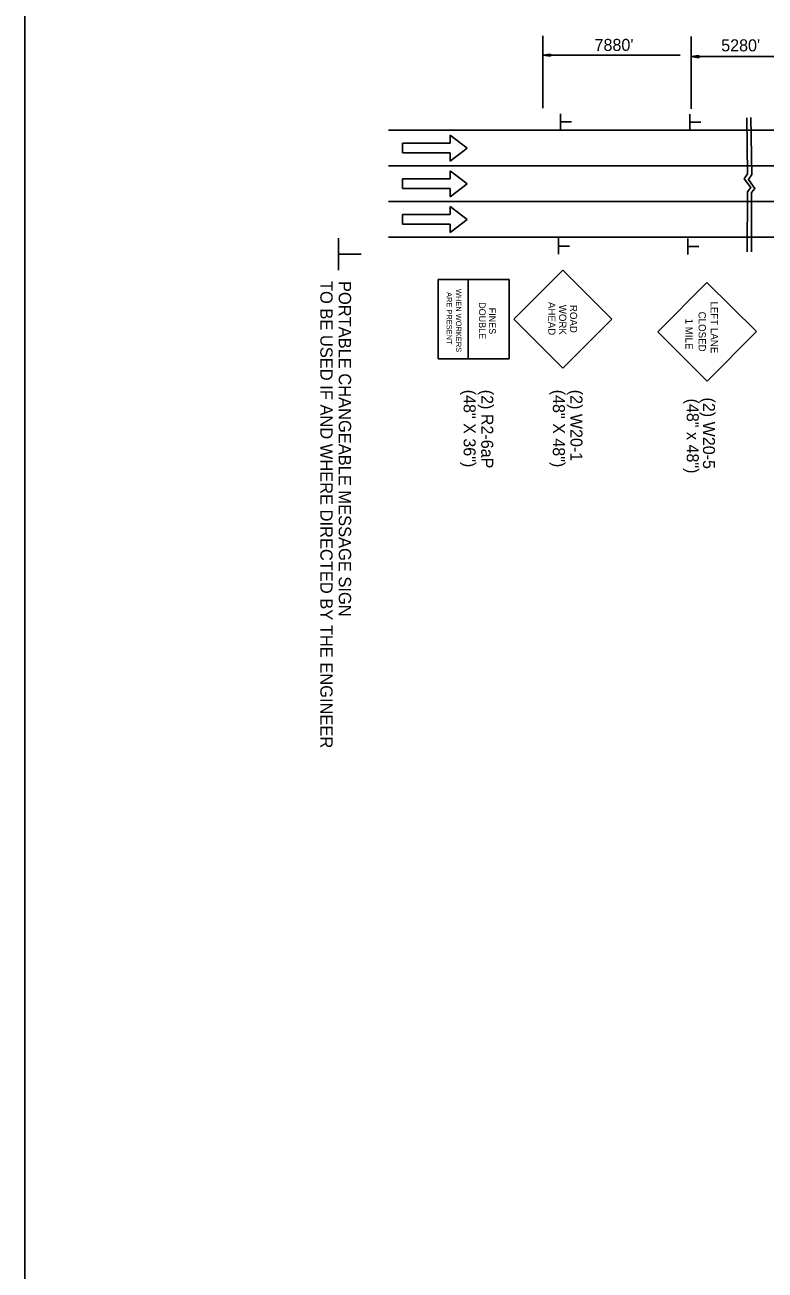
# Model space of a CAD drawing. Extents: x -100 to 745, y -1581 to -107.
# Drawn here: x 175.4 to 211.5, y -460.6 to -399.9 of the extents above; entities that cross this region are included whole.
import ezdxf

# ---------------------------------------------------------------- set-up
doc = ezdxf.new("R2010")
doc.units = 0
for name, color, linetype in [('Default', 7, 'Continuous'), ('R_Contour Annot', 7, 'Continuous'), ('R_Draft', 7, 'Continuous')]:
    doc.layers.add(name, color=color, linetype=linetype)

msp = doc.modelspace()

# ---------------------------------------------------------------- linework, layer by layer
at = {"layer": 'Default'}
for p, q in [((200.647, -400.39), (200.647, -403.911)), ((207.863, -400.419), (207.863, -403.94)), ((201.022, -401.275), (200.647, -401.332)), ((200.647, -401.332), (207.334, -401.332)), ((201.022, -401.388), (200.647, -401.332)), ((201.022, -401.285), (200.71, -401.332)), ((201.022, -401.379), (200.71, -401.332)), ((201.022, -401.294), (200.774, -401.332)), ((201.022, -401.369), (200.774, -401.332)), ((201.022, -401.304), (200.837, -401.332)), ((201.022, -401.36), (200.837, -401.332)), ((201.022, -401.313), (200.9, -401.332)), ((201.022, -401.35), (200.9, -401.332)), ((201.022, -401.323), (200.963, -401.332)), ((201.022, -401.34), (200.963, -401.332)), ((201.022, -401.388), (201.022, -401.275)), ((208.238, -401.342), (207.863, -401.398)), ((207.863, -401.398), (213.082, -401.398)), ((208.238, -401.455), (207.863, -401.398)), ((208.238, -401.351), (207.926, -401.398)), ((208.238, -401.445), (207.926, -401.398)), ((208.238, -401.361), (207.99, -401.398)), ((208.238, -401.436), (207.99, -401.398)), ((208.238, -401.37), (208.053, -401.398)), ((208.238, -401.426), (208.053, -401.398)), ((208.238, -401.38), (208.116, -401.398)), ((208.238, -401.417), (208.116, -401.398)), ((208.238, -401.39), (208.179, -401.398)), ((208.238, -401.407), (208.179, -401.398)), ((208.238, -401.455), (208.238, -401.342)), ((201.499, -404.968), (201.499, -404.185)), ((207.801, -404.984), (207.801, -404.202)), ((201.51, -404.579), (202.044, -404.579)), ((207.813, -404.595), (208.347, -404.595)), ((193.119, -404.99), (199.997, -404.99)), ((196.128, -405.227), (196.128, -405.622)), ((196.128, -405.227), (196.949, -405.859)), ((199.997, -404.99), (203.422, -404.99)), ((203.422, -404.99), (210.084, -404.99)), ((210.084, -404.99), (216.984, -404.99)), ((196.128, -405.622), (193.803, -405.622)), ((193.803, -405.622), (193.803, -406.097)), ((196.949, -405.859), (196.128, -406.492)), ((196.128, -406.097), (193.803, -406.097)), ((196.128, -406.097), (196.128, -406.492)), ((193.119, -406.729), (200.073, -406.729)), ((196.128, -406.966), (196.128, -407.361)), ((196.128, -406.966), (196.949, -407.598)), ((200.073, -406.729), (203.966, -406.729)), ((203.966, -406.729), (210.084, -406.729)), ((210.084, -406.729), (216.984, -406.729)), ((196.128, -407.361), (193.803, -407.361)), ((193.803, -407.361), (193.803, -407.835)), ((196.128, -407.835), (193.803, -407.835)), ((196.949, -407.598), (196.128, -408.23)), ((196.128, -407.835), (196.128, -408.23)), ((193.119, -408.467), (200.073, -408.467)), ((200.073, -408.467), (203.966, -408.467)), ((203.966, -408.467), (210.084, -408.467)), ((210.084, -408.467), (216.984, -408.467)), ((196.128, -408.704), (196.128, -409.099)), ((196.128, -408.704), (196.949, -409.336)), ((196.128, -409.099), (193.803, -409.099)), ((193.803, -409.099), (193.803, -409.574)), ((196.128, -409.574), (193.803, -409.574)), ((196.949, -409.336), (196.128, -409.969)), ((196.128, -409.574), (196.128, -409.969)), ((190.692, -411.81), (190.692, -410.246)), ((193.119, -410.206), (200.002, -410.206)), ((200.002, -410.206), (203.427, -410.206)), ((201.402, -411.032), (201.402, -410.25)), ((203.427, -410.206), (210.084, -410.206)), ((207.704, -411.049), (207.704, -410.266)), ((210.084, -410.206), (216.984, -410.206)), ((201.413, -410.643), (201.947, -410.643)), ((207.716, -410.66), (208.25, -410.66)), ((190.715, -411.032), (191.783, -411.032)), ((199.234, -414.197), (201.622, -411.806)), ((204.013, -414.197), (201.622, -411.806)), ((196.999, -416.128), (196.999, -412.266)), ((206.24, -414.816), (208.642, -412.406)), ((211.05, -414.807), (208.642, -412.406)), ((201.622, -416.587), (199.234, -414.197)), ((201.622, -416.587), (204.013, -414.197)), ((208.65, -417.217), (206.24, -414.816)), ((208.65, -417.217), (211.05, -414.807))]:
    msp.add_line(p, q, dxfattribs=at)
for points in [[(210.579, -404.379), (210.62, -407.11), (210.458, -407.352), (210.775, -407.785), (210.608, -407.985), (210.607, -410.92)], [(210.779, -404.376), (210.821, -407.152), (210.658, -407.393), (210.975, -407.826), (210.808, -408.026), (210.808, -410.917)]]:
    msp.add_lwpolyline(points, dxfattribs=at)
msp.add_lwpolyline([(199.001, -412.266), (195.549, -412.266), (195.549, -416.128), (199.001, -416.128)], close=True, dxfattribs=at)
at = {"layer": 'R_Contour Annot'}
msp.add_lwpolyline([(175.406, -370.582), (345.406, -370.582), (345.406, -480.582), (175.406, -480.582)], close=True, dxfattribs=at)
at = {"layer": 'R_Draft'}
msp.add_lwpolyline([(175.406, -370.582), (175.406, -480.582), (345.406, -480.582), (345.406, -370.582)], close=True, dxfattribs=at)

# ---------------------------------------------------------------- texts
at = {"layer": 'Default'}
for s, p in [("7880'", (203.163, -401.124)), ("5280'", (209.334, -401.145))]:
    msp.add_text(s, height=0.5862, dxfattribs=at).set_placement(p)
for s, height, rotation, p in [('TO BE USED IF AND WHERE DIRECTED BY THE ENGINEER', 0.59997, 270, (189.8, -412.338)), ('PORTABLE CHANGEABLE MESSAGE SIGN', 0.59997, 270, (190.7, -412.338)), ('ARE PRESENT', 0.26221, 270, (195.953, -412.879)), ('WHEN WORKERS', 0.26221, 270, (196.413, -412.727)), ('DOUBLE', 0.3278, 270, (197.53, -413.37)), ('FINES', 0.3278, 270, (198.021, -413.641)), ('AHEAD', 0.3522, 270.00057, (200.906, -413.361)), ('WORK', 0.352, 270.00004, (201.435, -413.499)), ('ROAD', 0.3521, 270.00045, (201.963, -413.506)), ('CLOSED', 0.3543, 270.10034, (208.231, -413.834)), ('LEFT LANE', 0.3544, 270.10045, (208.821, -413.337)), ('1 MILE', 0.3567, 270.00057, (207.59, -414.17)), ('(48" X 36")', 0.5862, 270, (196.784, -417.639)), ('(2) R2-6aP', 0.5862, 270, (197.641, -417.639)), ('(48" X 48")', 0.5862, 270, (201.131, -417.639)), ('(2) W20-1', 0.5862, 270, (201.988, -417.639)), ('(48" x 48")', 0.5862, 270, (207.656, -418.07)), ('(2) W20-5', 0.5862, 270, (208.446, -418.017))]:
    msp.add_text(s, height=height, rotation=rotation, dxfattribs=at).set_placement(p)

doc.saveas('drawing.dxf')
